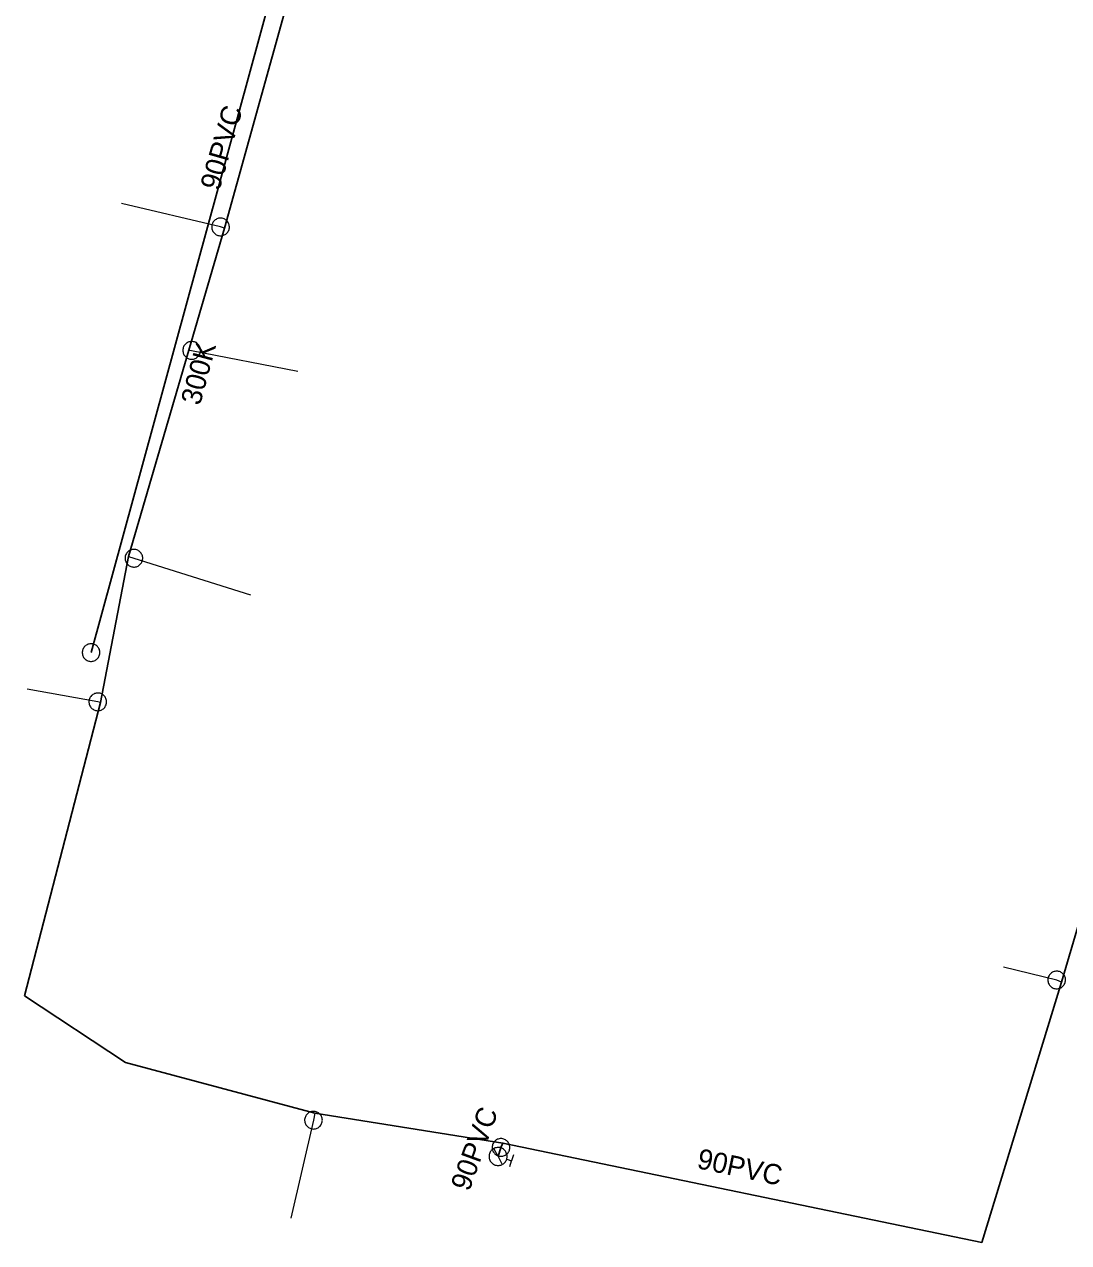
# Model space of a CAD drawing. Extents: x -741806 to -738704, y -1059275 to -1055387.
# Drawn here: x -740759.7 to -740708, y -1057940.6 to -1057880.2 of the extents above; entities that cross this region are included whole.
import ezdxf

# ---------------------------------------------------------------- set-up
doc = ezdxf.new("R2010")
doc.units = 0
doc.header["$LTSCALE"] = 0.4
for name, color, linetype, lineweight in [('2', 7, 'Continuous', 25), ('21', 7, 'Continuous', 13), ('3', 7, 'Continuous', 13), ('50', 7, 'Continuous', 13), ('51', 7, 'Continuous', 13), ('52', 7, 'Continuous', 25)]:
    doc.layers.add(name, color=color, linetype=linetype, lineweight=lineweight)
doc.layers.add('5', color=7, linetype='Continuous')
doc.layers.add('53', color=7, linetype='Continuous')

msp = doc.modelspace()

# ---------------------------------------------------------------- linework, layer by layer
at = {"layer": '2'}
msp.add_line((-740756.37, -1057911.35), (-740743.93, -1057865.84), dxfattribs=at)
at = {"layer": '21'}
for points in [[(-740749.763, -1057890.341), (-740749.96, -1057890.28), (-740754.866, -1057889.122)], [(-740751.526, -1057896.376), (-740751.39, -1057896.389), (-740746.136, -1057897.422)], [(-740754.51, -1057906.588), (-740754.25, -1057906.679), (-740748.469, -1057908.487)], [(-740755.899, -1057913.818), (-740756.039, -1057913.79), (-740759.535, -1057913.156)], [(-740708.335, -1057927.666), (-740708.57, -1057927.56), (-740711.201, -1057926.923)], [(-740745.291, -1057934.147), (-740745.359, -1057934.5), (-740746.48, -1057939.351)]]:
    msp.add_lwpolyline(points, dxfattribs=at)
at = {"layer": '3'}
msp.add_lwpolyline([(-740756.254, -1057910.927), (-740756.298, -1057910.918), (-740756.343, -1057910.913), (-740756.39, -1057910.913), (-740756.434, -1057910.917), (-740756.479, -1057910.927), (-740756.524, -1057910.94), (-740756.565, -1057910.959), (-740756.605, -1057910.981), (-740756.642, -1057911.009), (-740756.676, -1057911.039), (-740756.707, -1057911.073), (-740756.735, -1057911.11), (-740756.757, -1057911.149), (-740756.776, -1057911.191), (-740756.791, -1057911.234), (-740756.801, -1057911.279), (-740756.805, -1057911.325), (-740756.806, -1057911.37), (-740756.801, -1057911.416), (-740756.791, -1057911.461), (-740756.777, -1057911.504), (-740756.76, -1057911.546), (-740756.736, -1057911.586), (-740756.71, -1057911.623), (-740756.679, -1057911.658), (-740756.645, -1057911.688), (-740756.609, -1057911.715), (-740756.569, -1057911.739), (-740756.527, -1057911.757), (-740756.483, -1057911.771), (-740756.439, -1057911.781), (-740756.394, -1057911.786), (-740756.348, -1057911.787), (-740756.302, -1057911.782), (-740756.258, -1057911.773), (-740756.213, -1057911.759), (-740756.172, -1057911.74), (-740756.132, -1057911.717), (-740756.095, -1057911.691), (-740756.061, -1057911.661), (-740756.03, -1057911.627), (-740756.002, -1057911.59), (-740755.979, -1057911.551), (-740755.961, -1057911.509), (-740755.947, -1057911.465), (-740755.936, -1057911.42), (-740755.931, -1057911.375), (-740755.931, -1057911.329), (-740755.936, -1057911.283), (-740755.946, -1057911.238), (-740755.96, -1057911.195), (-740755.977, -1057911.153), (-740756.001, -1057911.113), (-740756.027, -1057911.076), (-740756.058, -1057911.042), (-740756.092, -1057911.011), (-740756.128, -1057910.984), (-740756.168, -1057910.961), (-740756.21, -1057910.942), (-740756.253, -1057910.927)], dxfattribs=at)
at = {"layer": '50'}
for p, q in [((-740736.223, -1057936.298), (-740736.431, -1057935.901)), ((-740736.223, -1057936.298), (-740736.018, -1057936.692)), ((-740735.796, -1057936.43), (-740735.556, -1057936.505)), ((-740735.647, -1057936.798), (-740735.556, -1057936.505)), ((-740735.465, -1057936.21), (-740735.556, -1057936.505))]:
    msp.add_line(p, q, dxfattribs=at)
msp.add_lwpolyline([(-740736.359, -1057936.721), (-740736.311, -1057936.733), (-740736.265, -1057936.742), (-740736.218, -1057936.743), (-740736.172, -1057936.739), (-740736.128, -1057936.733), (-740736.081, -1057936.719), (-740736.038, -1057936.702), (-740735.995, -1057936.681), (-740735.956, -1057936.657), (-740735.921, -1057936.625), (-740735.888, -1057936.593), (-740735.857, -1057936.557), (-740735.834, -1057936.516), (-740735.813, -1057936.475), (-740735.796, -1057936.432), (-740735.785, -1057936.387), (-740735.777, -1057936.343), (-740735.776, -1057936.295), (-740735.779, -1057936.248), (-740735.786, -1057936.2), (-740735.799, -1057936.157), (-740735.815, -1057936.113), (-740735.837, -1057936.072), (-740735.862, -1057936.033), (-740735.892, -1057935.996), (-740735.925, -1057935.963), (-740735.961, -1057935.935), (-740736.001, -1057935.907), (-740736.043, -1057935.889), (-740736.085, -1057935.87), (-740736.132, -1057935.858), (-740736.178, -1057935.852), (-740736.223, -1057935.85), (-740736.271, -1057935.852), (-740736.317, -1057935.86), (-740736.362, -1057935.871), (-740736.405, -1057935.89), (-740736.448, -1057935.91), (-740736.488, -1057935.937), (-740736.522, -1057935.966), (-740736.556, -1057936.001), (-740736.584, -1057936.037), (-740736.61, -1057936.074), (-740736.632, -1057936.119), (-740736.648, -1057936.162), (-740736.659, -1057936.206), (-740736.665, -1057936.253), (-740736.668, -1057936.3), (-740736.666, -1057936.346), (-740736.658, -1057936.393), (-740736.646, -1057936.437), (-740736.629, -1057936.482), (-740736.608, -1057936.522), (-740736.583, -1057936.561), (-740736.551, -1057936.596), (-740736.52, -1057936.631), (-740736.483, -1057936.66), (-740736.443, -1057936.683), (-740736.402, -1057936.704)], close=True, dxfattribs=at)
at = {"layer": '51'}
for points in [[(-740750.377, -1057890.15), (-740750.388, -1057890.193), (-740750.395, -1057890.238), (-740750.397, -1057890.285), (-740750.394, -1057890.33), (-740750.386, -1057890.375), (-740750.374, -1057890.42), (-740750.356, -1057890.462), (-740750.335, -1057890.503), (-740750.309, -1057890.54), (-740750.28, -1057890.575), (-740750.247, -1057890.608), (-740750.211, -1057890.636), (-740750.173, -1057890.661), (-740750.132, -1057890.681), (-740750.089, -1057890.696), (-740750.044, -1057890.708), (-740749.999, -1057890.715), (-740749.953, -1057890.716), (-740749.907, -1057890.713), (-740749.862, -1057890.705), (-740749.818, -1057890.692), (-740749.776, -1057890.676), (-740749.735, -1057890.654), (-740749.697, -1057890.629), (-740749.662, -1057890.599), (-740749.63, -1057890.566), (-740749.602, -1057890.531), (-740749.577, -1057890.492), (-740749.557, -1057890.451), (-740749.541, -1057890.408), (-740749.53, -1057890.364), (-740749.524, -1057890.319), (-740749.522, -1057890.272), (-740749.525, -1057890.227), (-740749.533, -1057890.182), (-740749.545, -1057890.137), (-740749.562, -1057890.095), (-740749.583, -1057890.054), (-740749.609, -1057890.017), (-740749.638, -1057889.982), (-740749.671, -1057889.95), (-740749.707, -1057889.921), (-740749.746, -1057889.897), (-740749.786, -1057889.876), (-740749.83, -1057889.861), (-740749.874, -1057889.849), (-740749.92, -1057889.843), (-740749.965, -1057889.841), (-740750.011, -1057889.844), (-740750.056, -1057889.852), (-740750.1, -1057889.865), (-740750.143, -1057889.881), (-740750.183, -1057889.903), (-740750.221, -1057889.928), (-740750.257, -1057889.958), (-740750.289, -1057889.991), (-740750.317, -1057890.026), (-740750.341, -1057890.065), (-740750.361, -1057890.106), (-740750.377, -1057890.149)], [(-740750.953, -1057896.389), (-740750.955, -1057896.344), (-740750.962, -1057896.299), (-740750.974, -1057896.254), (-740750.99, -1057896.212), (-740751.011, -1057896.171), (-740751.036, -1057896.132), (-740751.065, -1057896.097), (-740751.097, -1057896.064), (-740751.133, -1057896.036), (-740751.171, -1057896.011), (-740751.212, -1057895.99), (-740751.255, -1057895.973), (-740751.299, -1057895.961), (-740751.344, -1057895.954), (-740751.39, -1057895.952), (-740751.436, -1057895.954), (-740751.481, -1057895.961), (-740751.525, -1057895.973), (-740751.568, -1057895.99), (-740751.609, -1057896.011), (-740751.647, -1057896.036), (-740751.683, -1057896.064), (-740751.715, -1057896.097), (-740751.744, -1057896.132), (-740751.769, -1057896.171), (-740751.79, -1057896.212), (-740751.806, -1057896.254), (-740751.818, -1057896.299), (-740751.825, -1057896.344), (-740751.828, -1057896.39), (-740751.825, -1057896.435), (-740751.818, -1057896.48), (-740751.806, -1057896.525), (-740751.79, -1057896.567), (-740751.769, -1057896.608), (-740751.744, -1057896.647), (-740751.715, -1057896.682), (-740751.683, -1057896.715), (-740751.647, -1057896.743), (-740751.609, -1057896.768), (-740751.568, -1057896.789), (-740751.525, -1057896.806), (-740751.481, -1057896.817), (-740751.436, -1057896.825), (-740751.39, -1057896.827), (-740751.344, -1057896.825), (-740751.299, -1057896.817), (-740751.255, -1057896.806), (-740751.212, -1057896.789), (-740751.171, -1057896.768), (-740751.133, -1057896.743), (-740751.097, -1057896.715), (-740751.065, -1057896.682), (-740751.036, -1057896.647), (-740751.011, -1057896.608), (-740750.99, -1057896.567), (-740750.974, -1057896.525), (-740750.962, -1057896.48), (-740750.955, -1057896.435), (-740750.953, -1057896.39)], [(-740753.838, -1057906.825), (-740753.825, -1057906.782), (-740753.816, -1057906.737), (-740753.812, -1057906.69), (-740753.814, -1057906.646), (-740753.82, -1057906.6), (-740753.83, -1057906.555), (-740753.846, -1057906.512), (-740753.865, -1057906.47), (-740753.89, -1057906.432), (-740753.917, -1057906.396), (-740753.949, -1057906.362), (-740753.984, -1057906.332), (-740754.021, -1057906.306), (-740754.061, -1057906.284), (-740754.104, -1057906.267), (-740754.148, -1057906.254), (-740754.193, -1057906.245), (-740754.238, -1057906.242), (-740754.284, -1057906.243), (-740754.33, -1057906.25), (-740754.374, -1057906.26), (-740754.417, -1057906.275), (-740754.459, -1057906.295), (-740754.498, -1057906.319), (-740754.534, -1057906.347), (-740754.568, -1057906.379), (-740754.597, -1057906.413), (-740754.623, -1057906.451), (-740754.645, -1057906.491), (-740754.663, -1057906.534), (-740754.675, -1057906.577), (-740754.684, -1057906.622), (-740754.687, -1057906.668), (-740754.686, -1057906.713), (-740754.68, -1057906.759), (-740754.669, -1057906.804), (-740754.654, -1057906.847), (-740754.635, -1057906.889), (-740754.61, -1057906.927), (-740754.583, -1057906.963), (-740754.551, -1057906.997), (-740754.516, -1057907.027), (-740754.478, -1057907.052), (-740754.438, -1057907.075), (-740754.396, -1057907.092), (-740754.352, -1057907.105), (-740754.307, -1057907.113), (-740754.262, -1057907.117), (-740754.215, -1057907.115), (-740754.17, -1057907.109), (-740754.125, -1057907.098), (-740754.082, -1057907.084), (-740754.041, -1057907.064), (-740754.002, -1057907.04), (-740753.965, -1057907.012), (-740753.932, -1057906.98), (-740753.903, -1057906.946), (-740753.877, -1057906.908), (-740753.855, -1057906.867), (-740753.838, -1057906.826)], [(-740755.928, -1057913.367), (-740755.972, -1057913.357), (-740756.017, -1057913.353), (-740756.064, -1057913.353), (-740756.109, -1057913.358), (-740756.154, -1057913.368), (-740756.198, -1057913.382), (-740756.239, -1057913.402), (-740756.279, -1057913.424), (-740756.315, -1057913.452), (-740756.349, -1057913.483), (-740756.379, -1057913.517), (-740756.407, -1057913.554), (-740756.429, -1057913.594), (-740756.447, -1057913.636), (-740756.461, -1057913.68), (-740756.471, -1057913.725), (-740756.475, -1057913.77), (-740756.475, -1057913.816), (-740756.469, -1057913.862), (-740756.459, -1057913.907), (-740756.444, -1057913.95), (-740756.426, -1057913.991), (-740756.402, -1057914.031), (-740756.376, -1057914.068), (-740756.344, -1057914.102), (-740756.31, -1057914.132), (-740756.273, -1057914.158), (-740756.233, -1057914.181), (-740756.191, -1057914.199), (-740756.147, -1057914.214), (-740756.103, -1057914.222), (-740756.058, -1057914.227), (-740756.011, -1057914.226), (-740755.966, -1057914.222), (-740755.921, -1057914.212), (-740755.877, -1057914.197), (-740755.836, -1057914.178), (-740755.796, -1057914.155), (-740755.76, -1057914.127), (-740755.726, -1057914.097), (-740755.696, -1057914.062), (-740755.668, -1057914.025), (-740755.647, -1057913.985), (-740755.628, -1057913.944), (-740755.614, -1057913.9), (-740755.604, -1057913.855), (-740755.601, -1057913.809), (-740755.6, -1057913.764), (-740755.606, -1057913.718), (-740755.616, -1057913.673), (-740755.631, -1057913.63), (-740755.649, -1057913.588), (-740755.673, -1057913.549), (-740755.699, -1057913.512), (-740755.731, -1057913.478), (-740755.765, -1057913.447), (-740755.802, -1057913.421), (-740755.842, -1057913.398), (-740755.884, -1057913.38), (-740755.927, -1057913.367)], [(-740708.967, -1057927.379), (-740708.984, -1057927.421), (-740708.996, -1057927.464), (-740709.004, -1057927.51), (-740709.007, -1057927.555), (-740709.004, -1057927.601), (-740708.998, -1057927.647), (-740708.986, -1057927.691), (-740708.97, -1057927.734), (-740708.949, -1057927.775), (-740708.925, -1057927.813), (-740708.896, -1057927.849), (-740708.864, -1057927.882), (-740708.829, -1057927.911), (-740708.791, -1057927.936), (-740708.75, -1057927.957), (-740708.707, -1057927.974), (-740708.663, -1057927.986), (-740708.618, -1057927.994), (-740708.572, -1057927.996), (-740708.526, -1057927.994), (-740708.481, -1057927.987), (-740708.437, -1057927.976), (-740708.394, -1057927.959), (-740708.353, -1057927.939), (-740708.314, -1057927.914), (-740708.278, -1057927.885), (-740708.246, -1057927.854), (-740708.217, -1057927.818), (-740708.192, -1057927.78), (-740708.17, -1057927.739), (-740708.154, -1057927.697), (-740708.142, -1057927.653), (-740708.134, -1057927.607), (-740708.131, -1057927.562), (-740708.134, -1057927.516), (-740708.14, -1057927.47), (-740708.152, -1057927.426), (-740708.168, -1057927.383), (-740708.189, -1057927.343), (-740708.213, -1057927.304), (-740708.242, -1057927.268), (-740708.274, -1057927.235), (-740708.31, -1057927.207), (-740708.347, -1057927.181), (-740708.389, -1057927.16), (-740708.431, -1057927.143), (-740708.476, -1057927.132), (-740708.52, -1057927.123), (-740708.566, -1057927.121), (-740708.612, -1057927.123), (-740708.657, -1057927.131), (-740708.702, -1057927.141), (-740708.744, -1057927.158), (-740708.785, -1057927.178), (-740708.824, -1057927.203), (-740708.86, -1057927.232), (-740708.892, -1057927.264), (-740708.922, -1057927.3), (-740708.947, -1057927.338), (-740708.967, -1057927.378)], [(-740745.443, -1057934.928), (-740745.398, -1057934.935), (-740745.353, -1057934.937), (-740745.306, -1057934.934), (-740745.262, -1057934.926), (-740745.218, -1057934.913), (-740745.175, -1057934.896), (-740745.135, -1057934.874), (-740745.096, -1057934.849), (-740745.062, -1057934.819), (-740745.03, -1057934.787), (-740745.002, -1057934.751), (-740744.977, -1057934.712), (-740744.956, -1057934.671), (-740744.941, -1057934.628), (-740744.93, -1057934.583), (-740744.923, -1057934.538), (-740744.921, -1057934.492), (-740744.925, -1057934.447), (-740744.933, -1057934.401), (-740744.946, -1057934.357), (-740744.963, -1057934.315), (-740744.984, -1057934.274), (-740745.01, -1057934.236), (-740745.039, -1057934.201), (-740745.072, -1057934.169), (-740745.109, -1057934.141), (-740745.147, -1057934.117), (-740745.189, -1057934.097), (-740745.231, -1057934.081), (-740745.276, -1057934.069), (-740745.321, -1057934.064), (-740745.366, -1057934.062), (-740745.413, -1057934.065), (-740745.457, -1057934.073), (-740745.501, -1057934.085), (-740745.544, -1057934.102), (-740745.584, -1057934.124), (-740745.623, -1057934.149), (-740745.657, -1057934.179), (-740745.689, -1057934.212), (-740745.717, -1057934.248), (-740745.742, -1057934.287), (-740745.762, -1057934.328), (-740745.778, -1057934.371), (-740745.789, -1057934.415), (-740745.796, -1057934.461), (-740745.796, -1057934.507), (-740745.794, -1057934.552), (-740745.786, -1057934.597), (-740745.773, -1057934.642), (-740745.756, -1057934.684), (-740745.735, -1057934.724), (-740745.709, -1057934.762), (-740745.68, -1057934.797), (-740745.647, -1057934.829), (-740745.61, -1057934.858), (-740745.572, -1057934.882), (-740745.53, -1057934.902), (-740745.488, -1057934.918), (-740745.444, -1057934.928)], [(-740736.26, -1057936.247), (-740736.219, -1057936.264), (-740736.175, -1057936.276), (-740736.129, -1057936.284), (-740736.084, -1057936.287), (-740736.038, -1057936.285), (-740735.992, -1057936.278), (-740735.948, -1057936.266), (-740735.905, -1057936.251), (-740735.865, -1057936.23), (-740735.826, -1057936.206), (-740735.79, -1057936.177), (-740735.757, -1057936.145), (-740735.727, -1057936.11), (-740735.702, -1057936.072), (-740735.681, -1057936.031), (-740735.664, -1057935.988), (-740735.652, -1057935.944), (-740735.644, -1057935.899), (-740735.642, -1057935.853), (-740735.644, -1057935.807), (-740735.651, -1057935.762), (-740735.662, -1057935.718), (-740735.678, -1057935.675), (-740735.698, -1057935.634), (-740735.723, -1057935.595), (-740735.752, -1057935.559), (-740735.783, -1057935.527), (-740735.819, -1057935.497), (-740735.857, -1057935.472), (-740735.898, -1057935.45), (-740735.94, -1057935.434), (-740735.984, -1057935.422), (-740736.03, -1057935.414), (-740736.075, -1057935.411), (-740736.121, -1057935.414), (-740736.167, -1057935.42), (-740736.21, -1057935.432), (-740736.254, -1057935.447), (-740736.294, -1057935.468), (-740736.333, -1057935.493), (-740736.369, -1057935.521), (-740736.402, -1057935.553), (-740736.43, -1057935.589), (-740736.456, -1057935.626), (-740736.477, -1057935.667), (-740736.495, -1057935.71), (-740736.506, -1057935.754), (-740736.514, -1057935.799), (-740736.517, -1057935.845), (-740736.515, -1057935.891), (-740736.508, -1057935.936), (-740736.497, -1057935.98), (-740736.48, -1057936.023), (-740736.461, -1057936.064), (-740736.436, -1057936.103), (-740736.407, -1057936.139), (-740736.375, -1057936.171), (-740736.34, -1057936.201), (-740736.301, -1057936.226), (-740736.261, -1057936.246)]]:
    msp.add_lwpolyline(points, dxfattribs=at)
at = {"layer": '52'}
for points in [[(-740759.671, -1057928.335), (-740755.899, -1057913.818), (-740754.51, -1057906.588), (-740749.763, -1057890.341), (-740742.598, -1057864.585), (-740739, -1057851.635), (-740734.098, -1057834.034), (-740731.769, -1057823.959), (-740731.035, -1057821.527), (-740726.859, -1057805.99), (-740724.506, -1057798.436), (-740717.215, -1057772.777), (-740714.807, -1057763.593), (-740714.546, -1057762.394), (-740708.688, -1057741.976), (-740702.958, -1057721.108), (-740699.87, -1057708.35), (-740697.699, -1057698.53), (-740697.223, -1057697.027), (-740691.452, -1057683.465), (-740676.844, -1057679.298), (-740642.039, -1057681.06)], [(-740642.109, -1057681.277), (-740646.892, -1057698.923), (-740650.491, -1057712.355), (-740660.688, -1057748.311), (-740662.27, -1057754.375), (-740668.706, -1057779.97), (-740672.41, -1057794.838), (-740675.62, -1057807.1), (-740678.732, -1057817.242), (-740686.252, -1057845.788), (-740688.638, -1057855.325), (-740689.649, -1057859.271), (-740690.811, -1057862.723), (-740693.23, -1057874.22), (-740696.844, -1057886.129), (-740704.081, -1057912.448), (-740704.55, -1057914.862), (-740708.335, -1057927.666), (-740712.272, -1057940.561)], [(-740712.272, -1057940.561), (-740735.98, -1057935.631), (-740745.291, -1057934.147), (-740754.66, -1057931.642), (-740759.671, -1057928.335)], [(-740735.98, -1057935.631), (-740736.079, -1057935.85), (-740736.219, -1057936.3)]]:
    msp.add_lwpolyline(points, dxfattribs=at)

# ---------------------------------------------------------------- texts
at = {"layer": '5'}
msp.add_text('300K', height=1, rotation=75, dxfattribs=at).set_placement((-740750.978, -1057899.153))
at = {"layer": '53'}
for rotation, p in [(74, (-740750.023, -1057888.517)), (70, (-740737.654, -1057938.062)), (348, (-740726.423, -1057936.866))]:
    msp.add_text('90PVC ', height=1, rotation=rotation, dxfattribs=at).set_placement(p)

doc.saveas('drawing.dxf')
